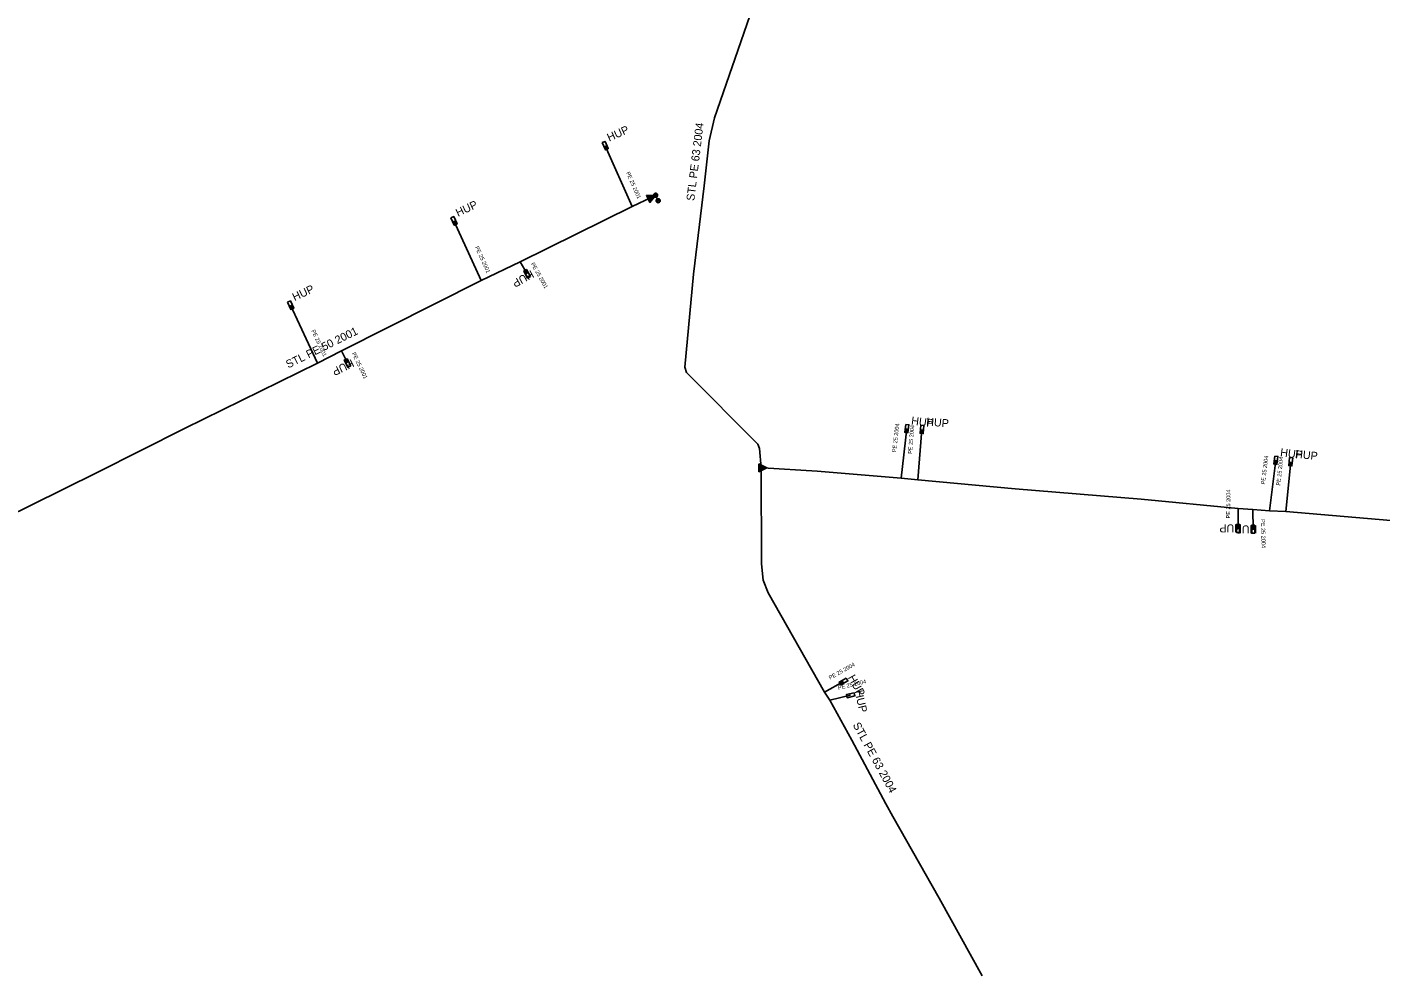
# Model space of a CAD drawing. Extents: x -741240 to -740302, y -1028024 to -1027535.
# Drawn here: x -740998.7 to -740829.5, y -1028023.6 to -1027905 of the extents above; entities that cross this region are included whole.
import ezdxf

# ---------------------------------------------------------------- set-up
doc = ezdxf.new("R2010")
doc.units = 0
for name, color, linetype in [('ST Úsek p_ípojky - provoz', 7, 'Continuous'), ('ST Úsek plynovodu - provoz', 7, 'Continuous'), ('ST_HUP_22_23_popis', 7, 'Continuous'), ('Vrstva 1', 7, 'Continuous')]:
    doc.layers.add(name, color=color, linetype=linetype)

msp = doc.modelspace()

# ---------------------------------------------------------------- linework, layer by layer
at = {"layer": 'ST Úsek p_ípojky - provoz'}
for points in [[(-740923.05, -1027927.4), (-740926.41, -1027919.81)], [(-740941.9, -1027936.65), (-740945.31, -1027929.21)], [(-740937.03, -1027934.32), (-740936.18, -1027935.83)], [(-740962.38, -1027946.98), (-740965.73, -1027939.75)], [(-740959.36, -1027945.43), (-740958.62, -1027946.97)], [(-740889.42, -1027961.35), (-740888.71, -1027955.16)], [(-740887.34, -1027961.58), (-740886.82, -1027955.27)], [(-740843.37, -1027965.46), (-740842.59, -1027959.12)], [(-740841.36, -1027965.52), (-740840.72, -1027959.31)], [(-740847.3, -1027965.17), (-740847.32, -1027967.64)], [(-740845.48, -1027965.29), (-740845.42, -1027967.74)], [(-740898.99, -1027988.1), (-740896.61, -1027986.77)], [(-740898.33, -1027989.1), (-740895.74, -1027988.49)]]:
    msp.add_lwpolyline(points, dxfattribs=at)
at = {"layer": 'ST Úsek plynovodu - provoz'}
for points in [[(-740904.17, -1027891.35), (-740908.34, -1027903.59), (-740912.76, -1027916.33), (-740913.41, -1027919.19), (-740914.04, -1027924.84), (-740915.38, -1027935.88), (-740916.46, -1027947.48), (-740916.24, -1027948.17), (-740907.33, -1027957.11), (-740907.11, -1027957.65), (-740906.9, -1027960.06)], [(-741010.53, -1027970.95), (-741001.37, -1027966.3), (-740998.14, -1027964.75), (-740989.9, -1027960.64), (-740978.99, -1027955.17), (-740962.38, -1027946.98), (-740959.36, -1027945.43), (-740941.9, -1027936.65), (-740937.03, -1027934.32), (-740923.05, -1027927.4), (-740920.59, -1027926.23)], [(-740920.59, -1027926.23), (-740920.11, -1027926.01)], [(-740906.9, -1027960.06), (-740906.88, -1027972.08), (-740906.66, -1027974.1), (-740906.04, -1027975.7), (-740898.99, -1027988.1), (-740898.33, -1027989.1), (-740895.59, -1027994.12), (-740891.33, -1028002.05), (-740890.45, -1028003.66), (-740884.69, -1028013.87), (-740879.29, -1028023.57)], [(-740906.9, -1027960.06), (-740906.69, -1027960.06)], [(-740906.69, -1027960.06), (-740899.91, -1027960.49), (-740889.42, -1027961.35), (-740887.34, -1027961.58), (-740875.19, -1027962.71), (-740859.41, -1027963.99), (-740847.3, -1027965.17), (-740845.48, -1027965.29), (-740843.37, -1027965.46), (-740841.36, -1027965.52), (-740828.21, -1027966.67), (-740810.98, -1027968.1), (-740797.51, -1027969.34), (-740795.59, -1027969.61), (-740795.35, -1027969.64), (-740793.47, -1027969.85), (-740783.45, -1027970.45), (-740778.94, -1027970.29), (-740774.16, -1027969.4), (-740762.89, -1027966.32), (-740754.51, -1027964.2), (-740752.85, -1027963.88), (-740751.75, -1027963.31), (-740751.46, -1027963.2)]]:
    msp.add_lwpolyline(points, dxfattribs=at)
at = {"layer": 'Vrstva 1'}
for p, q in [((-740919.9, -1027926.46), (-740920.11, -1027926.01)), ((-740920.11, -1027926.01), (-740919.9, -1027926.47))]:
    msp.add_line(p, q, dxfattribs=at)
for points in [[(-740926.8, -1027919.43), (-740926.43, -1027919.27), (-740926.02, -1027920.18), (-740926.39, -1027920.35)], [(-740921.25, -1027925.99), (-740920.83, -1027926.9), (-740920.13, -1027926.02)], [(-740920.81, -1027926.71), (-740920.34, -1027926.12), (-740921.09, -1027926.1)], [(-740920.54, -1027926.21), (-740920.93, -1027926.2), (-740920.78, -1027926.52)], [(-740919.99, -1027926.23), (-740920.02, -1027926.24), (-740920.04, -1027926.25), (-740920.06, -1027926.26), (-740920.09, -1027926.26), (-740920.11, -1027926.26), (-740920.14, -1027926.26), (-740920.16, -1027926.26), (-740920.18, -1027926.25), (-740920.21, -1027926.24), (-740920.23, -1027926.23), (-740920.25, -1027926.22), (-740920.27, -1027926.2), (-740920.29, -1027926.19), (-740920.3, -1027926.17), (-740920.32, -1027926.15), (-740920.33, -1027926.13), (-740920.34, -1027926.1), (-740920.35, -1027926.08), (-740920.36, -1027926.06), (-740920.36, -1027926.03), (-740920.36, -1027926.01), (-740920.36, -1027925.98), (-740920.36, -1027925.96), (-740920.35, -1027925.94), (-740920.34, -1027925.91), (-740920.33, -1027925.89), (-740920.32, -1027925.87), (-740920.3, -1027925.85), (-740920.29, -1027925.83), (-740920.27, -1027925.82), (-740920.25, -1027925.8), (-740920.23, -1027925.79), (-740920.2, -1027925.78), (-740920.18, -1027925.77), (-740920.16, -1027925.76), (-740920.13, -1027925.76), (-740920.11, -1027925.76), (-740920.08, -1027925.76), (-740920.06, -1027925.76), (-740920.04, -1027925.77), (-740920.01, -1027925.78), (-740919.99, -1027925.79), (-740919.97, -1027925.8), (-740919.95, -1027925.82), (-740919.93, -1027925.83), (-740919.92, -1027925.85), (-740919.9, -1027925.87), (-740919.89, -1027925.89), (-740919.88, -1027925.92), (-740919.87, -1027925.94), (-740919.86, -1027925.96), (-740919.86, -1027925.99), (-740919.86, -1027926.01), (-740919.86, -1027926.04), (-740919.86, -1027926.06), (-740919.87, -1027926.08), (-740919.88, -1027926.11), (-740919.89, -1027926.13), (-740919.9, -1027926.15), (-740919.92, -1027926.17), (-740919.93, -1027926.19), (-740919.95, -1027926.2), (-740919.97, -1027926.22)], [(-740919.96, -1027925.93), (-740919.95, -1027925.94), (-740919.94, -1027925.96), (-740919.94, -1027925.98), (-740919.94, -1027925.99), (-740919.93, -1027926.01), (-740919.94, -1027926.03), (-740919.94, -1027926.04), (-740919.94, -1027926.06), (-740919.95, -1027926.08), (-740919.96, -1027926.09), (-740919.97, -1027926.11), (-740919.98, -1027926.12), (-740919.99, -1027926.13), (-740920, -1027926.15), (-740920.01, -1027926.16), (-740920.03, -1027926.16), (-740920.04, -1027926.17), (-740920.06, -1027926.18), (-740920.08, -1027926.18), (-740920.09, -1027926.18), (-740920.11, -1027926.18), (-740920.13, -1027926.18), (-740920.14, -1027926.18), (-740920.16, -1027926.18), (-740920.18, -1027926.17), (-740920.19, -1027926.16), (-740920.21, -1027926.15), (-740920.22, -1027926.14), (-740920.23, -1027926.13), (-740920.25, -1027926.12), (-740920.26, -1027926.11), (-740920.27, -1027926.09), (-740920.27, -1027926.08), (-740920.28, -1027926.06), (-740920.28, -1027926.04), (-740920.28, -1027926.03), (-740920.28, -1027926.01), (-740920.28, -1027925.99), (-740920.28, -1027925.97), (-740920.28, -1027925.96), (-740920.27, -1027925.94), (-740920.26, -1027925.93), (-740920.26, -1027925.91), (-740920.25, -1027925.9), (-740920.23, -1027925.89), (-740920.22, -1027925.87), (-740920.21, -1027925.86), (-740920.19, -1027925.85), (-740920.18, -1027925.85), (-740920.16, -1027925.84), (-740920.14, -1027925.84), (-740920.13, -1027925.84), (-740920.11, -1027925.83), (-740920.09, -1027925.84), (-740920.07, -1027925.84), (-740920.06, -1027925.84), (-740920.04, -1027925.85), (-740920.03, -1027925.86), (-740920.01, -1027925.87), (-740920, -1027925.87), (-740919.99, -1027925.89), (-740919.97, -1027925.9), (-740919.96, -1027925.91)], [(-740920.24, -1027926.08), (-740920.25, -1027926.07), (-740920.25, -1027926.05), (-740920.26, -1027926.04), (-740920.26, -1027926.02), (-740920.26, -1027926.01), (-740920.26, -1027925.99), (-740920.26, -1027925.98), (-740920.25, -1027925.97), (-740920.25, -1027925.95), (-740920.24, -1027925.94), (-740920.23, -1027925.93), (-740920.23, -1027925.91), (-740920.22, -1027925.9), (-740920.2, -1027925.89), (-740920.19, -1027925.88), (-740920.18, -1027925.88), (-740920.17, -1027925.87), (-740920.15, -1027925.87), (-740920.14, -1027925.86), (-740920.12, -1027925.86), (-740920.11, -1027925.86), (-740920.09, -1027925.86), (-740920.08, -1027925.86), (-740920.07, -1027925.87), (-740920.05, -1027925.87), (-740920.04, -1027925.88), (-740920.03, -1027925.89), (-740920.01, -1027925.89), (-740920, -1027925.9), (-740919.99, -1027925.91), (-740919.98, -1027925.93), (-740919.98, -1027925.94), (-740919.97, -1027925.95), (-740919.97, -1027925.97), (-740919.96, -1027925.98), (-740919.96, -1027926), (-740919.96, -1027926.01), (-740919.96, -1027926.03), (-740919.96, -1027926.04), (-740919.97, -1027926.05), (-740919.97, -1027926.07), (-740919.98, -1027926.08), (-740919.99, -1027926.09), (-740919.99, -1027926.11), (-740920, -1027926.12), (-740920.02, -1027926.13), (-740920.03, -1027926.13), (-740920.04, -1027926.14), (-740920.05, -1027926.15), (-740920.07, -1027926.15), (-740920.08, -1027926.16), (-740920.1, -1027926.16), (-740920.11, -1027926.16), (-740920.13, -1027926.16), (-740920.14, -1027926.16), (-740920.15, -1027926.15), (-740920.17, -1027926.15), (-740920.18, -1027926.14), (-740920.19, -1027926.13), (-740920.21, -1027926.13), (-740920.22, -1027926.11), (-740920.23, -1027926.1), (-740920.23, -1027926.09)], [(-740920.18, -1027926.04), (-740920.18, -1027926.04), (-740920.18, -1027926.03), (-740920.18, -1027926.02), (-740920.18, -1027926.02), (-740920.19, -1027926.01), (-740920.18, -1027926), (-740920.18, -1027925.99), (-740920.18, -1027925.99), (-740920.18, -1027925.98), (-740920.18, -1027925.97), (-740920.17, -1027925.97), (-740920.17, -1027925.96), (-740920.16, -1027925.96), (-740920.16, -1027925.95), (-740920.15, -1027925.95), (-740920.15, -1027925.94), (-740920.14, -1027925.94), (-740920.13, -1027925.94), (-740920.12, -1027925.94), (-740920.12, -1027925.93), (-740920.11, -1027925.93), (-740920.1, -1027925.93), (-740920.09, -1027925.94), (-740920.09, -1027925.94), (-740920.08, -1027925.94), (-740920.07, -1027925.94), (-740920.07, -1027925.95), (-740920.06, -1027925.95), (-740920.06, -1027925.96), (-740920.05, -1027925.96), (-740920.05, -1027925.97), (-740920.04, -1027925.97), (-740920.04, -1027925.98), (-740920.04, -1027925.99), (-740920.04, -1027926), (-740920.04, -1027926), (-740920.03, -1027926.01), (-740920.04, -1027926.02), (-740920.04, -1027926.03), (-740920.04, -1027926.03), (-740920.04, -1027926.04), (-740920.04, -1027926.05), (-740920.05, -1027926.05), (-740920.05, -1027926.06), (-740920.06, -1027926.06), (-740920.06, -1027926.07), (-740920.07, -1027926.07), (-740920.07, -1027926.08), (-740920.08, -1027926.08), (-740920.09, -1027926.08), (-740920.1, -1027926.08), (-740920.1, -1027926.08), (-740920.11, -1027926.09), (-740920.12, -1027926.08), (-740920.13, -1027926.08), (-740920.13, -1027926.08), (-740920.14, -1027926.08), (-740920.15, -1027926.08), (-740920.15, -1027926.07), (-740920.16, -1027926.07), (-740920.16, -1027926.06), (-740920.17, -1027926.06), (-740920.17, -1027926.05)], [(-740945.7, -1027928.84), (-740945.34, -1027928.67), (-740944.92, -1027929.58), (-740945.28, -1027929.75)], [(-740935.76, -1027936.17), (-740936.11, -1027936.36), (-740936.6, -1027935.49), (-740936.25, -1027935.29)], [(-740966.12, -1027939.38), (-740965.76, -1027939.21), (-740965.34, -1027940.12), (-740965.7, -1027940.29)], [(-740958.22, -1027947.33), (-740958.58, -1027947.51), (-740959.02, -1027946.61), (-740958.66, -1027946.43)], [(-740888.85, -1027954.64), (-740888.45, -1027954.69), (-740888.57, -1027955.68), (-740888.97, -1027955.63)], [(-740886.97, -1027954.76), (-740886.58, -1027954.79), (-740886.66, -1027955.79), (-740887.06, -1027955.75)], [(-740842.73, -1027958.6), (-740842.33, -1027958.65), (-740842.46, -1027959.64), (-740842.85, -1027959.59)], [(-740840.87, -1027958.79), (-740840.47, -1027958.83), (-740840.58, -1027959.83), (-740840.97, -1027959.79)], [(-740907.19, -1027959.56), (-740907.19, -1027960.56), (-740906.19, -1027960.06)], [(-740907.09, -1027960.4), (-740906.41, -1027960.06), (-740907.09, -1027959.72)], [(-740906.64, -1027960.06), (-740906.99, -1027959.89), (-740906.99, -1027960.24)], [(-740847.12, -1027968.14), (-740847.52, -1027968.14), (-740847.52, -1027967.14), (-740847.12, -1027967.14)], [(-740845.21, -1027968.24), (-740845.61, -1027968.25), (-740845.63, -1027967.25), (-740845.23, -1027967.24)], [(-740896.28, -1027986.35), (-740896.08, -1027986.7), (-740896.95, -1027987.19), (-740897.15, -1027986.84)], [(-740895.3, -1027988.18), (-740895.21, -1027988.57), (-740896.18, -1027988.8), (-740896.27, -1027988.41)]]:
    msp.add_lwpolyline(points, close=True, dxfattribs=at)
for centre, radius in [((-740919.79, -1027926.69), 0.249), ((-740919.89, -1027926.72), 0.0614), ((-740919.7, -1027926.64), 0.0614)]:
    msp.add_circle(centre, radius, dxfattribs=at)

# ---------------------------------------------------------------- texts
at = {"layer": 'ST Úsek p_ípojky - provoz'}
for s, rotation, p in [('PE 25 2001', 293.8756, (-740923.82, -1027923.2)), ('PE 25 2001', 294.6172, (-740942.7, -1027932.51)), ('PE 25 2001', 299.392, (-740935.73, -1027934.58)), ('PE 25 2001', 294.854, (-740963.15, -1027942.94)), ('PE 25 2001', 295.6652, (-740958.09, -1027945.77)), ('PE 25 2004', 83.4669, (-740890.06, -1027958.14)), ('PE 25 2004', 85.3026, (-740888.07, -1027958.34)), ('PE 25 2004', 83.0275, (-740843.97, -1027962.17)), ('PE 25 2004', 84.126, (-740842.04, -1027962.31)), ('PE 25 2004', 89.5131, (-740848.31, -1027966.4)), ('PE 25 2004', 271.4023, (-740844.45, -1027966.49)), ('PE 25 2004', 29.2364, (-740898.29, -1027986.56)), ('PE 25 2004', 13.2615, (-740897.26, -1027987.82))]:
    msp.add_text(s, height=0.5, rotation=rotation, dxfattribs=at).set_placement(p)
at = {"layer": 'ST Úsek plynovodu - provoz'}
for s, rotation, p in [('STL PE 63 2004', 83.0782, (-740915.28, -1027926.75)), ('STL PE 50 2001', 26.2468, (-740966.02, -1027947.66)), ('STL PE 63 2004', 298.5608, (-740895.5, -1027992.2))]:
    msp.add_text(s, height=1, rotation=rotation, dxfattribs=at).set_placement(p)
at = {"layer": 'ST_HUP_22_23_popis'}
for rotation, p in [(24, (-740925.91, -1027919.31)), (25, (-740944.81, -1027928.71)), (209, (-740935.68, -1027935.33)), (25, (-740965.23, -1027939.25)), (206, (-740958.12, -1027946.47)), (353, (-740888.21, -1027954.66)), (355, (-740886.32, -1027954.77)), (353, (-740842.09, -1027958.62)), (354, (-740840.22, -1027958.81)), (180, (-740846.82, -1027967.14)), (181, (-740844.92, -1027967.24)), (299.24, (-740896.11, -1027986.27)), (283, (-740895.24, -1027987.99))]:
    msp.add_text('HUP', height=1, rotation=rotation, dxfattribs=at).set_placement(p)

doc.saveas('drawing.dxf')
